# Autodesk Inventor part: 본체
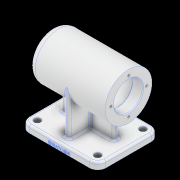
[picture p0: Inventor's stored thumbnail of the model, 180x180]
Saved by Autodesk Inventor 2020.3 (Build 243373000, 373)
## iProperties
Created: 2020-10
Part Number: 본체
Material: 알루미늄 6061
Document SubType Name: Modeling
Designer: EZDESIGN
Density: 2.7 g/cm^3
Appearance: 알루미늄 - 평지
Mass: 1025.65 g
Surface Area: 759.531 cm^2
Volume: 379.871 cm^3
Author: EZDESIGN
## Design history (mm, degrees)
sketch "스케치1"
  geometry: L1 (56, -45)-(-56, -45); L2 (-56, -45)-(-56, 45); L3 (-56, 45)-(56, 45); L4 (56, 45)-(56, -45); 1 further point
  constraints: 8 end point, 2 parallel, 1 horizontal, 1 perpendicular
  dimensions: "d0" = 112 distance between parallel lines of L4 L2; "d1" = 90 distance between parallel lines of L1 L3; "d2" = 45 distance from line of point (0, 0) L1; "d3" = 56 distance from line of point (0, 0) L2
extrude "돌출1" new body sketch "스케치1" distance "d4" = 10; taper "d5" = 0 deg
fillet "모깎기1" dims "d6" = 12
sketch "스케치2"
  geometry: L1 (-56, 33)-(-56, -33) reference; L2 (-44, -45)-(44, -45) reference; L3 (56, -33)-(56, 33) reference; L4 (44, 45)-(-44, 45) reference; A1 r 12 centre (-44, 33) between (-44, 45) and (-56, 33) reference; A2 r 12 centre (-44, -33) between (-56, -33) and (-44, -45) reference; A3 r 12 centre (44, -33) between (44, -45) and (56, -33) reference; A4 r 12 centre (44, 33) between (56, 33) and (44, 45) reference; 5 further points
  constraints: 4 coincident
hole "구멍1" sketch "스케치2" at (-44, 33), (44, 33), (44, -33), (-44, -33) diameter "d7" = 5.5; stored, may be unused: countersink angle "d11" = 90 deg, drill point angle "d13" = 118 deg; dims "d8" = 6, "d9" = 9.5, "d10" = 5.4, "d12" = 8
sketch "스케치3"
  geometry: L1 (-56, 74)-(56, 74); L2 (-44, 0)-(44, 0) reference; L3 (56, 10)-(56, 0) reference; L4 (-56, 74)-(-56, 108); L5 (-56, 108)-(56, 108); L6 (56, 108)-(56, 74); 1 further point
  constraints: 8 end point, 2 perpendicular, 1 horizontal, 1 point on line, 1 vertical
  dimensions: "d14" = 74 distance between parallel lines of L1 L2; "d15" = 112 distance of L1.start L1.end; "d16" = 68 diameter of L5 L1
revolve "회전1" sketch "스케치3" stored, may be unused: angle "d17" = 90 deg
fillet "모깎기2" dims "d18" = 10
sketch "스케치4"
  geometry: L1 (-50, 74)-(56, 74); L2 (44, 0)-(-44, 0) reference; L3 (56, 40)-(56, 108) reference; L4 (56, 74)-(56, 95); L5 (56, 95)-(41, 95); L6 (41, 95)-(41, 95); L7 (38, 98)-(-10, 98); L8 (-13, 95)-(-13, 95); L9 (-13, 95)-(-24.7, 95); L10 (-25, 94.7)-(-25, 91.5); L11 (-25, 91.5)-(-42.7, 91.5); L12 (-43, 91.2)-(-43, 90); L13 (-43, 90)-(-46.7, 90); L14 (-47, 89.7)-(-47, 84.5); L15 (-47, 84.5)-(-47, 84.5); L16 (-50, 81.5)-(-50, 74); A1 r 0.3 centre (-46.7, 89.7) between (-46.7, 90) and (-47, 89.7); A2 r 0.3 centre (-42.7, 91.2) between (-42.7, 91.5) and (-43, 91.2); A3 r 0.3 centre (-24.7, 94.7) between (-24.7, 95) and (-25, 94.7); A4 r 3 centre (-47, 81.5) between (-47, 84.5) and (-50, 81.5); A5 r 3 centre (-10, 95) between (-10, 98) and (-13, 95); A6 r 3 centre (38, 95) between (41, 95) and (38, 98); 5 further points
  constraints: 28 end point, 12 point on circle, 12 tangent, 8 perpendicular, 6 centre point, 5 point on line, 3 equal radius, 3 horizontal, 1 midpoint, 1 vertical
  dimensions: "d19" = 74 distance between parallel lines of L1 L2; "d20" = 42 diameter of L5 L1; "d21" = 15 distance between parallel lines of L6 L4; "d22" = 54 distance between parallel lines of L8 L6; "d23" = 48 diameter of L7 L1; "d24" = 42 diameter of L9 L1 (derived); "d25" = 12 distance between parallel lines of L10 L8; "d26" = 18 distance between parallel lines of L12 L10; "d27" = 4 distance between parallel lines of L14 L12; "d28" = 3 distance between parallel lines of L16 L14; "d29" = 35 diameter of L11 L1; "d30" = 32 diameter of L13 L1; "d31" = 21 diameter of L15 L1; "d32" = 0.3 radius of A1; "d33" = 0.3 radius of A2 (derived); "d34" = 3 radius of A4
revolve "회전2" sketch "스케치4" stored, may be unused: angle "d35" = 90 deg
sketch "스케치5" dims "d36" = 52
  geometry: C1 r 21 at (0, 0) reference; C2 r 34 at (0, 0) reference; 3 further points
  constraints: 2 vertical alignment, 1 coincident, 2 other
hole "구멍2" sketch "스케치5" at (0, 26) diameter "d37" = 3.242; stored, may be unused: countersink angle "d41" = 90 deg, drill point angle "d43" = 118 deg; dims "d38" = 8, "d39" = 9.5, "d40" = 5.4, "d42" = 11
chamfer "모따기1" distance "d47" = 1; stored, may be unused: second distance "d48" = 2, angle "d49" = 45 deg
sketch "스케치6"
  geometry: L1 (38, 4)-(38, -4); L2 (-38, -4)-(-38, 4); L3 (-4, 34)-(4, 34); L4 (4, -34)-(-4, -34); L5 (-38, 4)-(-4, 4); L6 (4, 4)-(38, 4); L7 (38, -4)-(4, -4); L8 (-4, -4)-(-38, -4); L9 (4, 34)-(4, 4); L10 (4, -4)-(4, -34); L11 (-4, -34)-(-4, -4); L12 (-4, 4)-(-4, 34); L13 (56, -33)-(56, 33) reference; L14 (-56, 33)-(-56, -33) reference; L15 (0, 0)-(14.578, 0); 4 further points
  constraints: 26 end point, 10 parallel, 4 horizontal, 4 midpoint, 4 perpendicular, 2 horizontal alignment, 2 vertical alignment, 1 other
  dimensions: "d50" = 8 distance of L4.start L4.end; "d51" = 8 distance of L3.start L3.end; "d52" = 8 distance of L1.start L1.end; "d53" = 8 distance of L2.start L2.end; "d54" = 18 distance between parallel lines of L13 L1; "d55" = 18 distance between parallel lines of L14 L2; "d56" = 68 distance between parallel lines of L3 L4
extrude "돌출2" join sketch "스케치6" stored distance "d57" = 10; taper "d58" = 0 deg
fillet "모깎기3" dims "d59" = 3
fillet "모깎기4" dims "d60" = 3
fillet "모깎기5" dims "d61" = 3
node "작업 평면1"
sketch "스케치7"
  geometry: L1 (100, 0)-(100, 7) reference; L2 (100, 0)-(88, 0) reference; 2 further points
  constraints: 1 other
  dimensions: "d63" = 56 distance from line of point (44, 3) L1; "d64" = 3 distance from line of point (44, 3) L2
feature "엠보싱1" sketch "스케치7" dims "d0" = 112, "d1" = 90, "d2" = 45, "d3" = 56, "d65" = 0.5, "d66" = 0
node "솔리드1"
pattern_circular "원형 패턴1" dims angle "d45" = 360 deg
node "투영된 루프1"
node "투영된 루프2"
feature "A9D066F2-1C7D-4E18-AEED-F7BC21143FA4" dims "d37" = 3.242, "d38" = 8, "d39" = 9.5, "d40" = 5.4, "d41" = 90 deg, "d42" = 11, "d43" = 118 deg
other parameters: "d62" = 7
